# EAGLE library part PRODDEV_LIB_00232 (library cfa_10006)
CFAG12864C
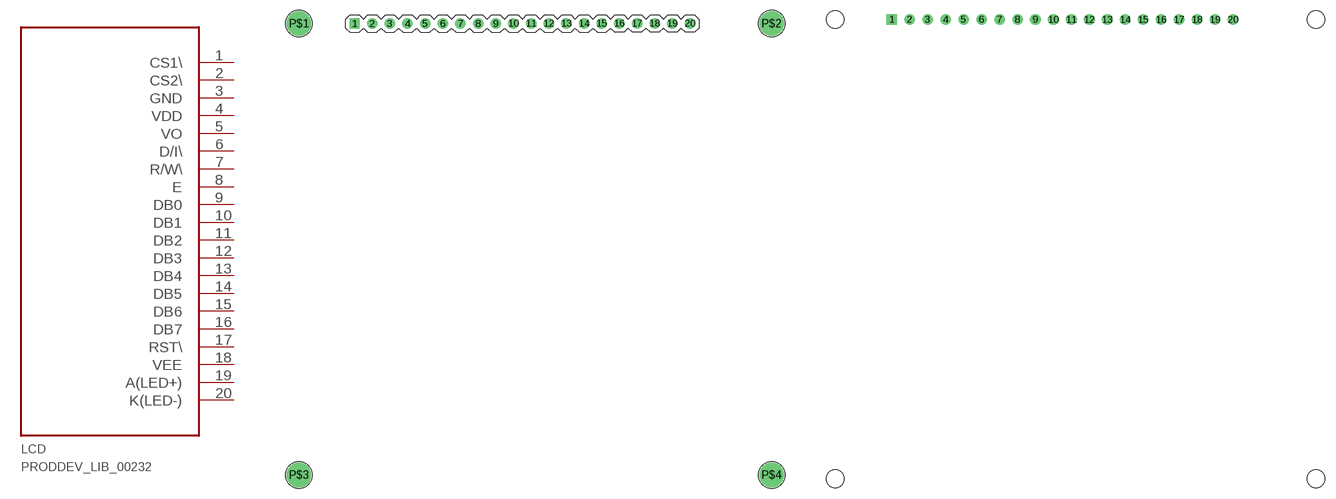
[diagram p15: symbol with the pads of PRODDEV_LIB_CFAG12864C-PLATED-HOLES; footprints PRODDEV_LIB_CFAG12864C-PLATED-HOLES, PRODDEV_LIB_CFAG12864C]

Designator prefix LCD

## PRODDEV_LIB_00232  [PRODDEV_LIB_CFAG12864C-PLATED-HOLES]
1  CS1\  in
2  CS2\  in
3  GND  pwr
4  VDD  pwr
5  VO  pas
6  D/I\  in
7  R/W\  in
8  E  in
9  DB0
10  DB1
11  DB2
12  DB3
13  DB4
14  DB5
15  DB6
16  DB7
17  RST\  in
18  VEE  pas
19  A(LED+)  pas
20  K(LED-)  pas

## PRODDEV_LIB_00232NON-PLATED-HOLES  [PRODDEV_LIB_CFAG12864C]
Pads as for PRODDEV_LIB_CFAG12864C-PLATED-HOLES

## Footprint PRODDEV_LIB_CFAG12864C-PLATED-HOLES (pad centres in mm)
drill 1 square: 1 0,0
drill 1 round: 2 2.54,0; 3 5.08,0; 4 7.62,0; 5 10.16,0; 6 12.7,0; 7 15.24,0; 8 17.78,0; 9 20.32,0; 10 22.86,0; 11 25.4,0; 12 27.94,0; 13 30.48,0; 14 33.02,0; 15 35.56,0; 16 38.1,0; 17 40.64,0; 18 43.18,0; 19 45.72,0; 20 48.26,0
drill 2.5 round: P$1 -8,0; P$2 60,0; P$3 -8,-64.92; P$4 60,-64.92

## Footprint PRODDEV_LIB_CFAG12864C (pad centres in mm)
drill 1 square: 1 0,0
drill 1 round: 2 2.54,0; 3 5.08,0; 4 7.62,0; 5 10.16,0; 6 12.7,0; 7 15.24,0; 8 17.78,0; 9 20.32,0; 10 22.86,0; 11 25.4,0; 12 27.94,0; 13 30.48,0; 14 33.02,0; 15 35.56,0; 16 38.1,0; 17 40.64,0; 18 43.18,0; 19 45.72,0; 20 48.26,0
hole 2.5 at -8,0
hole 2.5 at 60,0
hole 2.5 at -8,-64.92
hole 2.5 at 60,-64.92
